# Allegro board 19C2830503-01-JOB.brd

Outline 180.6 x 177.71 mm; copper layers: TOP, L2_GND, L3, L4_PWR, L5, L6_GND, L7_GND, L8, L9_PWR, L10, L11_GND, BOTTOM. Coordinates in mm from the lower left corner of the outline.
Outline path: 0,97.65 arc(0.04,97.84) 0.15,98.01 0.45,98.31 arc(0.62,98.42) 0.81,98.46 9.8,98.46 arc(10.51,98.75) 10.8,99.46 10.8,113.31 arc(10.51,114.02) 9.8,114.31 6.7,114.31 6.7,173.41 8.5,173.41 8.5,176.01 10.8,176.01 10.8,177.71 167,177.71 167,176.71 174.6,176.71 174.6,172.51 180.6,172.51 180.6,30.31 166.24,30.31 166.24,30.81 158,30.81 158,29.21 10.8,29.21 10.8,32.46 arc(10.51,33.17) 9.8,33.46 0.81,33.46 arc(0.62,33.5) 0.45,33.61 0.15,33.91 arc(0.04,34.08) 0,34.27 0,97.65

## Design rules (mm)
net group 25M_MMCX: nets 25M_MMCX 25M_MMCX_R
net group 50OHM(1-4): nets PHYSYNC RADSYNC
net group 5482S_LAN1_LINK_R: nets 5482S_LAN1_LINK_R LAN0_LED_RX
net group 5482S_LAN1_SPEED2_R: nets 5482S_LAN1_SPEED2_R LAN0_LED_LINK100
net group 5482S_LAN2_LINK_R: nets 5482S_LAN2_LINK_R LAN1_LED_RX
net group 5482S_LAN2_SPEED2_R: nets 5482S_LAN2_SPEED2_R LAN1_LED_LINK100
net group AMC_RP1CLKN: nets AMC_RP1CLKN RP1CLKN_C
net group AMC_RP1CLKP: nets AMC_RP1CLKP RP1CLKP_C
net group AMC_TIMO0: nets AMC_TIMO0 TCLKC_P
net group AMCC_P4_PCIE_TX1N: nets AMCC_P4_PCIE_TX1N AMCC_P4_PCIE_TX1N_C
net group AMCC_P4_PCIE_TX1P: nets AMCC_P4_PCIE_TX1P AMCC_P4_PCIE_TX1P_C
net group AMCC_P5_PCIE_TX2N: nets AMCC_P5_PCIE_TX2N AMCC_P5_PCIE_TX2N_C
net group AMCC_P5_PCIE_TX2P: nets AMCC_P5_PCIE_TX2P AMCC_P5_PCIE_TX2P_C
net group AVID_OEZ: nets AVID_OEZ N15783945
net group BSC_JTAG_TCK: nets BSC_JTAG_TCK N13662497
net group CLK1_ELF: nets CLK1_ELF N14872798
net group CLK1_REF_SEL: nets CLK1_REF_SEL N68057721
net group CLK2_ELF: nets CLK2_ELF N14873463
net group CLK2_REF_SEL: nets CLK2_REF_SEL N68049869
net group CLK3_ELF: nets CLK3_ELF N15625345
net group CLK3_REF_SEL: nets CLK3_REF_SEL N15625166
net group CVDD_PWR_MON: nets CVDD_PWR_MON CVDD_PWR_OK
net group DAC_VOUT: nets DAC_VOUT N18495232
net group DDR3_OTHER(10/9-15/13.5): nets SOC_DDR3A_EMRESETN SOC_DDR3B_EMRESETN
net group DIFFPAIR12: nets USB_RXN_R USB_RXP_R
net group DIFFPAIR13: nets USBDN_R USBDP_R
net group DIFFPAIR14: nets USB_TXN_R USB_TXP_R
net group DIFFPAIR26: nets VCTCXO_25M_CLKN_R VCTCXO_25M_CLKP_R
net group DIFFPAIR28: nets USB_DM1 USB_DP1
net group DP_FARM0_UCD_EA1: nets FARM0_UCD_EAN1 FARM0_UCD_EAP1
net group DP_FARM0_UCD_EA2: nets FARM0_UCD_EAN2 FARM0_UCD_EAP2
net group EMIFCE0Z: nets EMIFCE0Z SOC_EMIFCE0Z
net group EMU_EMU_00: nets EMU_EMU_00 EMU_EMU_00_R
net group EMU_EMU_01: nets EMU_EMU_01 EMU_EMU_01_R
net group EMU_TCKRTN: nets EMU_TCKRTN N16762531
net group EMU_TDI: nets EMU_TDI EMU_TDI_R
net group EMU_TDO: nets EMU_TDO EMU_TDO_R
net group EMU_TMS: nets EMU_TMS EMU_TMS_R
net group EMU_TRST#: nets EMU_TRST# EMU_TRST#_R
net group EXP_TP1: nets EXP_TP1 MCU_RESETSTATZ
net group EXP_TP2: nets EXP_TP2 EXT_PS#
net group FAN_PWM: nets FAN_PWM N16114816
net group FARM0_CSN1: nets FARM0_CSN1 N13251183
net group FARM0_CSN2: nets FARM0_CSN2 N13262989
net group FARM0_CSP1: nets FARM0_CSP1 N65094220
net group FARM0_CSP2: nets FARM0_CSP2 N13263135
net group FARM0_FF-1A: nets FARM0_FF-1A FARM0_FF-1A_L
net group FARM0_FF-2A: nets FARM0_FF-2A FARM0_FF-2A_L
net group FARM0_FF-3A: nets FARM0_FF-3A FARM0_FF-3A_L
net group FARM0_FF-4A: nets FARM0_FF-4A FARM0_FF-4A_L
net group FARM0_ILIM1: nets FARM0_ILIM1 N15094693
net group FARM0_ILIM2: nets FARM0_ILIM2 N13263091
net group FARM0_LSENES-1A: nets FARM0_LSENES-1A N13254474
net group FARM0_LSENES-2A: nets FARM0_LSENES-2A N13255208
net group FARM0_LSENES-3A: nets FARM0_LSENES-3A N13256024
net group FARM0_LSENES-4A: nets FARM0_LSENES-4A N13255844
net group FARM0_UCD_EAN4: nets FARM0_UCD_EAN4 N13257002
net group FARM1_FF-1A: nets FARM1_FF-1A FARM1_FF-1A_L
net group FARM1_FF-2A: nets FARM1_FF-2A FARM1_FF-2A_L
net group FARM1_FF-3A: nets FARM1_FF-3A FARM1_FF-3A_L
net group FARM1_FF-4A: nets FARM1_FF-4A FARM1_FF-4A_L
net group FARM1_ILIM2: nets FARM1_ILIM2 N17515515
net group FARM1_LSENES-1A: nets FARM1_LSENES-1A N14336954
net group FARM1_LSENES-2A: nets FARM1_LSENES-2A N14335646
net group FARM1_LSENES-3A: nets FARM1_LSENES-3A N14336112
net group FARM1_LSENES-4A: nets FARM1_LSENES-4A N14336022
net group FULL_RESETZ: nets FULL_RESETZ SW8-P1
net group GPS_ENABLE: nets GPS_ENABLE MCU_GPS_ENABLE
net group GPS_RF: nets GPS_RF N66015127
net group GPS_RTC_CLK: nets GPS_RTC_CLK GPS_RTC_CLK_R
net group GPS_UARTRXD: nets GPS_UARTRXD GPS_UARTRXD_R
net group HYPER0LINKCLKN_C: nets HYPER0_LINK_CLKN HYPER0LINKCLKN_C
net group HYPER0LINKCLKP_C: nets HYPER0_LINK_CLKP HYPER0LINKCLKP_C
net group HYPERLINK0_RXFLCLK: nets HYPERLINK0_RXFLCLK HYPERLINK0_RXFLCLK_R
net group HYPERLINK0_TXPMCLK: nets HYPERLINK0_TXPMCLK HYPERLINK0_TXPMCLK_R
net group HYPERLINK1_RXFLCLK: nets HYPERLINK1_RXFLCLK HYPERLINK1_RXFLCLK_R
net group HYPERLINK1_TXPMCLK: nets HYPERLINK1_TXPMCLK HYPERLINK1_TXPMCLK_R
net group LAN0_LED_LINK10: nets LAN0_LED_LINK10 P0_CONFIG5
net group LAN1_LED_LINK10: nets LAN1_LED_LINK10 P1_CONFIG5
net group LCD_A0: nets LCD_A0 N16319325
net group LED0_DUPLEX: nets LED0_DUPLEX P0_CONFIG3
net group LED_DUPLEX: nets LED_DUPLEX P1_CONFIG3
net group LED_TX: nets LED_TX P1_CONFIG0
net group MAIN_POWER_GOOD: nets MAIN_POWER_GOOD MAIN_POWER_GOOD_R
net group MAIN_POWER_START: nets MAIN_POWER_START MAIN_POWER_START_R
net group MCU_JTAG_TCK: nets MCU_JTAG_TCK N16188479
net group MCU_PA1_U0TX: nets MCU_PA1_U0TX MCU_UART_TX
net group MCU_SPI0_MISO: nets MCU_SPI0_MISO N68025736
net group MCU_SPI0_MOSI: nets MCU_SPI0_MOSI N68025719
net group MCU_SPI1_MOSI: nets MCU_SPI1_MOSI N13012268
net group MCU_U0RX: nets MCU_U0RX MCU_UART_RX
net group MCU_U1RX: nets MCU_U1RX SOC_UART0_TXD_3V3
net group MCUXOSC0: nets MCUXOSC0 MCUXOSC0_R
net group MMC_BLUE_LED: nets MMC_BLUE_LED N16865801
net group MMC_ENABLE_N: nets MMC_ENABLE_N N16053779
net group MMC_RED_LED: nets MMC_RED_LED N16865898
net group N12681649: nets N12681649 N12681653
net group N12681665: nets N12681665 N12681669
net group N13268184: nets N13268184 N13268208
net group N13268308: nets N13268308 N13268312
net group N14335704: nets N14335704 N14335728
net group N14335828: nets N14335828 N14335832
net group N14876495: nets N14876495 N14876735
net group N14876513: nets N14876513 N14876739
net group N14876577: nets N14876577 N14876667
net group N14876581: nets N14876581 N14876671
net group N15443451: nets N15443451 N15443455
net group N15443549: nets N15443549 N15443557
net group N15626537: nets N15626537 N16870591
net group N15633874: nets N15633874 N15633910
net group N15633892: nets N15633892 N15633914
net group N15634110: nets N15634110 N15634136
net group N15634114: nets N15634114 N15634140
net group N15634384: nets N15634384 N15634420
net group N15634388: nets N15634388 N15634424
net group N16169033: nets N16169033 N16169087
net group N16169055: nets N16169055 N16169091
net group N16169113: nets N16169113 N16169139
net group N16169117: nets N16169117 N16169161
net group N16577490: nets N16577490 N16762648
net group N16762689: nets N16762689 N16762695
net group N16826793: nets N16826793 N20002440
net group N16869469: nets N16869469 N68057761
net group N16870184: nets N16870184 N68049909
net group N43929984: nets N43929984 N43929986
net group N43930002: nets N43930002 N43930004
net group N44510240: nets N44510240 N44510256
net group N56425114: nets N56425114 N56425144
net group PCIE_CLKN: nets PCIE_CLKN PCIE_CLKN_R
net group PCIE_CLKP: nets PCIE_CLKP PCIE_CLKP_R
net group PCIECLK_MCU_PD: nets N16316172 PCIECLK_MCU_PD
net group PCIECLK_OE: nets N16572263 PCIECLK_OE
net group PCIECLKN_C: nets PCIECLKN_M PCIECLKN_MR
net group PCIECLKP_C: nets PCIECLKP_M PCIECLKP_MR
net group PHY_P0_XTAL1: nets PHY_P0_XTAL1 PHY_P0_XTAL1_R
net group PHY_P1_XTAL1: nets PHY_P1_XTAL1 PHY_P1_XTAL1_R
net group PLLLOCK_LED: nets N16865403 PLLLOCK_LED
net group PMBUS_ALERT: nets N14715464 PMBUS_ALERT
net group PMBUS_CLK: nets PMBUS_CLK PW_SEQ_SCL
net group PMBUS_CTL: nets N14715500 PMBUS_CTL
net group PMBUS_DAT: nets PMBUS_DAT PW_SEQ_SDA
net group REFCK_N: nets REFCK_N REFCK_N_C
net group REFCK_P: nets REFCK_P REFCK_P_C
net group SOC_EMU_02: nets SOC_EMU_02 SOC_EMU_02_R
net group SOC_EMU_03: nets SOC_EMU_03 SOC_EMU_03_R
net group SOC_EMU_04: nets SOC_EMU_04 SOC_EMU_04_R
net group SOC_EMU_05: nets SOC_EMU_05 SOC_EMU_05_R
net group SOC_EMU_06: nets SOC_EMU_06 SOC_EMU_06_R
net group SOC_EMU_07: nets SOC_EMU_07 SOC_EMU_07_R
net group SOC_EMU_08: nets SOC_EMU_08 SOC_EMU_08_R
net group SOC_EMU_09: nets SOC_EMU_09 SOC_EMU_09_R
net group SOC_EMU_10: nets SOC_EMU_10 SOC_EMU_10_R
net group SOC_EMU_11: nets SOC_EMU_11 SOC_EMU_11_R
net group SOC_EMU_12: nets SOC_EMU_12 SOC_EMU_12_R
net group SOC_EMU_13: nets SOC_EMU_13 SOC_EMU_13_R
net group SOC_EMU_14: nets SOC_EMU_14 SOC_EMU_14_R
net group SOC_EMU_15: nets SOC_EMU_15 SOC_EMU_15_R
net group SOC_EMU_16: nets SOC_EMU_16 SOC_EMU_16_R
net group SOC_EMU_17: nets SOC_EMU_17 SOC_EMU_17_R
net group SOC_EMU_18: nets SOC_EMU_18 SOC_EMU_18_R
net group SOC_EMU_19: nets SOC_EMU_19 SOC_EMU_19_R
net group SOC_EMU_20: nets SOC_EMU_20 SOC_EMU_20_R
net group SOC_EMU_21: nets SOC_EMU_21 SOC_EMU_21_R
net group SOC_EMU_22: nets SOC_EMU_22 SOC_EMU_22_R
net group SOC_EMU_23: nets SOC_EMU_23 SOC_EMU_23_R
net group SOC_EMU_24: nets SOC_EMU_24 SOC_EMU_24_R
net group SOC_EMU_25: nets SOC_EMU_25 SOC_EMU_25_R
net group SOC_EMU_26: nets SOC_EMU_26 SOC_EMU_26_R
net group SOC_EMU_27: nets SOC_EMU_27 SOC_EMU_27_R
net group SOC_EMU_28: nets SOC_EMU_28 SOC_EMU_28_R
net group SOC_EMU_29: nets SOC_EMU_29 SOC_EMU_29_R
net group SOC_EMU_30: nets SOC_EMU_30 SOC_EMU_30_R
net group SOC_EMU_31: nets SOC_EMU_31 SOC_EMU_31_R
net group SOC_EMU_32: nets SOC_EMU_32 SOC_EMU_32_R
net group SOC_EMU_33: nets SOC_EMU_33 SOC_EMU_33_R
net group SOC_GPIO_00: nets SOC_GPIO_00 SOC_GPIO_R00
net group SOC_GPIO_01: nets SOC_GPIO_01 SOC_GPIO_R01
net group SOC_GPIO_02: nets SOC_GPIO_02 SOC_GPIO_R02
net group SOC_GPIO_03: nets SOC_GPIO_03 SOC_GPIO_R03
net group SOC_GPIO_04: nets SOC_GPIO_04 SOC_GPIO_R04
net group SOC_GPIO_05: nets SOC_GPIO_05 SOC_GPIO_R05
net group SOC_GPIO_06: nets SOC_GPIO_06 SOC_GPIO_R06
net group SOC_GPIO_07: nets SOC_GPIO_07 SOC_GPIO_R07
net group SOC_GPIO_08: nets SOC_GPIO_08 SOC_GPIO_R08
net group SOC_GPIO_09: nets SOC_GPIO_09 SOC_GPIO_R09
net group SOC_GPIO_10: nets SOC_GPIO_10 SOC_GPIO_R10
net group SOC_GPIO_11: nets SOC_GPIO_11 SOC_GPIO_R11
net group SOC_GPIO_16: nets SOC_GPIO_16 SOC_GPIO_R16
net group SOC_POWER_GOOD: nets SOC_POWER_GOOD SOC_POWER_GOOD_R
net group SOC_POWER_START: nets SOC_POWER_START SOC_POWER_START_R
net group SOC_RESETSTATZ: nets N16800870 SOC_RESETSTATZ
net group SOC_SSP0_CLK: nets SOC_SSP0_CLK SOC_SSPCK_R
net group SOC_SSP0_MISO: nets N16007057 SOC_SSP0_MISO
net group SOC_SSP0_MOSI: nets SOC_SSP0_MOSI SOC_SSPMOSI_R
net group SOC_SSP1_CLK: nets N68010936 SOC_SSP1_CLK
net group SOC_SSP1_CS0: nets N15613486 SOC_SSP1_CS0
net group SOC_SSP1_MOSI: nets N68010938 SOC_SSP1_MOSI
net group SOC_SSP2_CLK: nets N16755468 SOC_SSP2_CLK
net group SOC_SSP2_CS0: nets N16815045 SOC_SSP2_CS0
net group SOC_SSP2_CS1: nets N16755452 SOC_SSP2_CS1
net group SOC_SSP2_CS2: nets N16755456 SOC_SSP2_CS2
net group SOC_SSP2_CS3: nets N16755460 SOC_SSP2_CS3
net group SOC_SSP2_MISO: nets N16809812 SOC_SSP2_MISO
net group SOC_TIMO1: nets SOC_TIMO1 SOC_TIMO1_R
net group SOC_UART0_TXD_V1P8: nets SOC_UART0_TXD_V1P8 UART0_TXD_R
net group SOC_UART1_RTS_V1P8: nets SOC_UART1_RTS_V1P8 UART1_RTS_R
net group SOC_UART1_TXD_1V8: nets SOC_UART1_TXD_1V8 UART1_TXD_R
net group SOC_XFI_CLKN: nets SOC_XFI_CLKN SOC_XFI_CLKN_R
net group SOC_XFI_CLKP: nets SOC_XFI_CLKP SOC_XFI_CLKP_R
net group SOCCLKSEL_R: nets SOC_CORECLKSEL SOCCLKSEL_R
net group SPI: nets N16809810 SOC_SSP2_MOSI
net group SW7-P1: nets SW7-P1 WARM_RESETZ
net group TCLKB_N: nets TCLKB_N TCLKB_N_C
net group TCLKB_P: nets TCLKB_P TCLKB_P_C
net group TCLKD_N: nets TCLKD_N TCLKD_N_C
net group TCLKD_P: nets TCLKD_P TCLKD_P_C
net group TRIP1: nets TRIP1 TRIP3
net group UCD_PWR_MON: nets UCD_PWR_MON UCD_PWR_OK
net group URTM_PS#: nets URTM_PS# URTM_PS#_R
net group USB: nets USB_TXN USB_TXP
net group USB_CLKN: nets USB_CLKN USB_CLKN_R
net group USB_CLKP: nets USB_CLKP USB_CLKP_R
net group VCC0V75_EN: nets VCC0V75_EN VCC0V75_EN_R
net group VCC1V2_EN: nets VCC1V2_EN VCC1V2_EN_R
net group VCC2V5_EN: nets VCC2V5_EN VCC2V5_EN_R
net group VCC3_LCD: nets N14810291 VCC3_LCD
net group VCC3V3_AUX_EN: nets VCC3_AUX_EN_R VCC3V3_AUX_EN
net group VCTCXO_25M_CLKN: nets VCTCXO_25M_CLKN VCTCXO_25M_CLKN_C
net group VCTCXO_25M_CLKP: nets VCTCXO_25M_CLKP VCTCXO_25M_CLKP_C
net group VID_OEZ: nets N15783905 VID_OEZ
net group VPP1V8: nets N16969569 VPP1V8_MON
net group 5482S_LAN1_SPEED1_R: nets 5482S_LAN1_SPEED1_R LAN0_LED_LINK1000 P0_CONFIG1 P0_CONFIG4
net group 5482S_LAN2_SPEED1_R: nets 5482S_LAN2_SPEED1_R LAN1_LED_LINK1000 P1_CONFIG1 P1_CONFIG4
net group AIF0_RXN_C: nets AIF0_RXN_C
net group AIF0_RXP_C: nets AIF0_RXP_C
net group AIF1_RXN_C: nets AIF1_RXN_C
net group AIF1_RXP_C: nets AIF1_RXP_C
net group AIF2_RXN_C: nets AIF2_RXN_C
net group AIF2_RXP_C: nets AIF2_RXP_C
net group AIF3_RXN_C: nets AIF3_RXN_C
net group AIF3_RXP_C: nets AIF3_RXP_C
net group AIF4_RXN_C: nets AIF4_RXN_C
net group AIF4_RXP_C: nets AIF4_RXP_C
net group AIF5_RXN_C: nets AIF5_RXN_C
net group AIF5_RXP_C: nets AIF5_RXP_C
net group ALTCORECLKN_C: nets ALT_CORE_CLKN
net group ALTCORECLKP_C: nets ALT_CORE_CLKP
net group ARMCLKN_C: nets ARM_CLKN
net group ARMCLKP_C: nets ARM_CLKP
net group AT_CLKN: nets AT_CLKN
net group AT_CLKP: nets AT_CLKP
net group BSC_JTAG_SRSTN: nets BSC_JTAG_SRSTN MCU_SRSTN_R N13662509
net group BSC_JTAG_TDI: nets BSC_JTAG_TDI MCU_JTAG_TDI N13662505
net group BSC_JTAG_TDO: nets BSC_JTAG_TDO MCU_JTAG_TDO N13662501
net group BSC_JTAG_TMS: nets BSC_JTAG_TMS MCU_JTAG_TMS N13662493
net group CLK_DIFF: nets VCC3V3_PCIE
net group CLK_SINGLE: nets CLK1_SYNC CLK2_SYNC GTX_CLK GTX_CLK_0 P0_CLKSEL P1_CLKSEL REFCLK1_PD# REFCLK2_PD# SIM_CLK TX_CLK TX_CLK_0
net group DDR3ACLKN_C: nets DDR3A_CLKN
net group DDR3ACLKP_C: nets DDR3A_CLKP
net group DDR3BCLKN_C: nets DDR3B_CLKN
net group DDR3BCLKP_C: nets DDR3B_CLKP
net group DSP_SCL_AMC: nets DSP_SCL_AMC EXP_SCL2_3V3 SOC_SCL_RTM
net group DSP_SDA_AMC: nets DSP_SDA_AMC EXP_SDA2_3V3 SOC_SDA_RTM
net group EMU_TCK: nets EMU_TCK EMU_TCK_R N17260565
net group FARM0_UCD_EAN3: nets FARM0_UCD_EAN3 FARM0_UCD_EAP3 N13256834
net group FARM1_AVGG2: nets FARM1_AVGG2
net group FARM1_CSN2: nets FARM1_CSN2 FARM1_CSP2 N14340048 N14340304 N14340850 N14340854
net group FARM1_SW_SHAPE1: nets N14634249
net group FARM1_UCD_EAN1: nets FARM1_UCD_EAN1 FARM1_UCD_EAP1 N14335250
net group FARM1_UCD_EAN2: nets FARM1_UCD_EAN2 FARM1_UCD_EAP2 N14336826
net group FARM1_UCD_EAN3: nets FARM1_UCD_EAN3 FARM1_UCD_EAP3 N14336882
net group FARM1_UCD_EAN4: nets FARM1_UCD_EAN4 FARM1_UCD_EAP4 N14336966
net group FARM1_UCD_EN: nets FARM1_UCD_EN FARM1_UCD_EN_L FARM1_UCD_EN_R
net group FT2232HL_RESET#1: nets FT2232HL_RESET#1 N12620052 N12620068 N12620494 N15576101
net group HEAD_UCD_CNTRL_L: nets HEAD_UCD_CNTRL_L UCD9244_EN UCD9244_EN_R
net group HYPER1LINKCLKN_C: nets HYPER1_LINK_CLKN
net group HYPER1LINKCLKP_C: nets HYPER1_LINK_CLKP
net group LAN: nets LAN0_TRD2_0N LAN0_TRD2_0P LAN0_TRD2_1N LAN0_TRD2_1P LAN0_TRD2_2N LAN0_TRD2_2P LAN0_TRD2_3N LAN0_TRD2_3P LAN1_TRD2_0N LAN1_TRD2_0P LAN1_TRD2_1N LAN1_TRD2_1P LAN1_TRD2_2N LAN1_TRD2_2P LAN1_TRD2_3N LAN1_TRD2_3P
net group MCU_RESET_SWZ: nets MCU_RESET_SWZ
net group MCU_SPI0: nets MCU_SPI0_CLK MCU_SPI0_CLK_1V8 MCU_SPI0_CS0Z MCU_SPI0_CS1Z MCU_SPI0_CS3Z MCU_SPI0_CS4Z MCU_SPI0_MISO_1V8 MCU_SPI0_MOSI_1V8
net group MCU_SPI1: nets MCU_SPI1_CLK
net group MMC_GA0: nets MMC_GA0 MMC_GA1 MMC_GA2 MMC_GAPU
net group N17761475: nets N56424980 N56425122 N56425140
net group N44510100: nets N44510176
net group PHY_RSTZ: nets PHY_RSTZ R_P0_LAN_RSTZ R_P1_LAN_RSTZ
net group SIM_IO: nets SIM_IO
net group SMBUS: nets SMB_SCL_IPMBL SMB_SDA_IPMBL SOC_MDC SOC_MDC_3V3 SOC_MDIO SOC_MDIO_3V3
net group SOC_GPIO_12: nets N16761112 SOC_GPIO_12 SOC_GPIO_R12
net group SOC_GPIO_13: nets N16761582 SOC_GPIO_13 SOC_GPIO_R13
net group SOC_GPIO_14: nets N16757437 SOC_GPIO_14 SOC_GPIO_R14
net group SOC_GPIO_15: nets N16758697 SOC_GPIO_15 SOC_GPIO_R15
net group SOC_SGMII0_RXN: nets SOC_SGMII0_RXN
net group SOC_SGMII0_RXP: nets SOC_SGMII0_RXP
net group SOC_SGMII0_TXN: nets SOC_SGMII0_TXN_C
net group SOC_SGMII0_TXP: nets SOC_SGMII0_TXP_C
net group SOC_SGMII1_RXN: nets SOC_SGMII1_RXN
net group SOC_SGMII1_RXP: nets SOC_SGMII1_RXP
net group SOC_SGMII1_TXN: nets SOC_SGMII1_TXN_C
net group SOC_SGMII1_TXP: nets SOC_SGMII1_TXP_C
net group SOC_SSP2_MOSI: nets N16755464
net group SOC_TIMO0: nets SOC_TIMO0 SOC_TIMO0_R TCLKC_N
net group SRIOSGMIICLKN_C: nets SRIO_SGMII_CLKN
net group SRIOSGMIICLKP_C: nets SRIO_SGMII_CLKP
net group UART: nets RS232_RX RS232_TX SOC_UART0_RXD_3V3
net group VCC5: nets N16826901 N16827414 VCC5_MON
net group VCC5_EN: nets VCC5_EN VCC5_EN_R1 VCC5_EN_R2
net group VCC5_VBUS: nets N12619718 N15576385 VCC5_VBUS
net group VCCA0V75: nets VCCA0V75_MON

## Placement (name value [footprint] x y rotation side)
AMC1  -  [GF-AMC-B]  2.05 65.96 90 top
ATT  DTSA-63K-V  [SW_2P_DTSA-63K-V_D]  176.75 124.16 90 top
B1  120_100MHz  [L0603]  113.16 173.74 90 bottom
B2  120_100MHz  [L0603]  125.09 173.86 270 top
B3  120_100MHz  [L0603]  129.29 173.86 90 top
B4  120_100MHz  [L0402]  170.18 171.07 270 top
B5  1K_100MHz  [L0603]  165.74 164.85 270 top
B6  1K_100MHz  [L0603]  165.74 162.94 270 top
B7  220_100MHz  [L0402]  128.65 133.86 180 top
B8  120_100MHz  [L0402]  123.06 133.48 180 top
B9  2200pF  [L_3P_70_63X35]  73.28 135.38 270 top
B10  2200pF  [L_3P_70_63X35]  40.77 125.98 90 top
B11  2200pF  [L_3P_70_63X35]  70.74 135.38 270 top
B12  2200pF  [L_3P_70_63X35]  43.08 124.79 0 top
B13  2200pF  [L_3P_70_63X35]  120.02 125.86 0 top
B14  2200pF  [L_3P_70_63X35]  89.13 108.61 180 top
B15  2200pF  [L_3P_70_63X35]  107.57 117.09 90 top
B16  470_100MHz  [L0603]  78.11 86.61 0 bottom
B17  100_100MHz  [L0603]  80.16 83.85 0 bottom
B20  100_100MHz  [L0603]  37.97 74.17 90 bottom
B22  90_100MHZ  [ACM2012]  162 115.85 0 top
B23  2200pF  [L_3P_70_63X35]  17.91 113.16 0 top
B24  90_100MHZ  [ACM2012]  162.05 111.76 0 top
B25  2200pF  [L_3P_70_63X35]  45.97 122.3 270 top
B27  120_100MHz  [L0402]  149.99 102.49 180 top
B28  0.1uF  [L_3P_87_79X53]  32.77 99.95 270 bottom
B29  0.1uF  [L_3P_87_79X53]  34.92 92.2 270 bottom
B30  120_100MHz  [L0402]  153.8 91.06 0 top
B31  2200pF  [L_3P_70_63X35]  24.51 89.92 0 top
B32  470_100MHz  [L0603]  79.04 75.56 180 bottom
B33  120_100MHz  [L0402]  149.99 78.1 180 top
B34  120_100MHz  [L0402]  153.8 76.19 0 top
B38  470_100MHz  [L0603]  64.16 74.8 180 bottom
B39  2200pF  [L_3P_70_63X35]  126.24 67.31 270 top
B41  470_100MHz  [L0603]  38.99 70.61 270 top
B43  1212_BEAD_0  [L0603]  36.7 55.25 270 top
B44  2200pF  [L_3P_70_63X35]  83.06 122.33 270 bottom
B45  470_100MHz  [L0603]  67.39 112.6 180 bottom
B46  1212_BEAD_0  [L0603]  35.31 82.8 0 bottom
B47  2200pF  [L_3P_70_63X35]  136.25 80.34 270 top
B48  120_100MHz  [L0402]  70.87 89.41 180 bottom
C1  0.1uF  [C0402]  160.88 171.07 0 bottom
C2  0.1uF  [C0402]  106.43 173.99 270 top
C3  0.1uF  [C0402]  147.07 173.23 180 top
C4  0.1uF  [C0402]  120.14 172.72 0 top
C5  0.1uF  [C0402]  127.89 172.21 270 top
C6  0.1uF  [C0402]  130.94 172.21 90 top
C7  10uF  [C0603]  161.67 171.07 270 top
C8  10uF  [C0805]  122.05 170.81 180 top
C9  1200pF  [C0603]  105.03 169.04 90 top
C10  0.01uF  [C0402]  109.47 173.99 180 bottom
C11  10uF  [C0805]  107.57 173.86 0 bottom
C12  10uF  [C0603]  144.83 169.65 180 top
C13  0.1uF  [C0402]  111.38 168.91 270 top
C14  8200pF  [C0603]  125.6 168.78 90 top
C15  10uF  [C0603]  162.69 167.51 180 top
C16  0.01uF  [C0402]  107.31 168.15 0 top
C17  0.1uF  [C0402]  160.66 167.77 90 top
C18  560pF  [C0402]  108.33 166.5 270 top
C19  0.1uF  [C0402]  144.53 166.12 270 top
C20  0.01uF  [C0402]  161.67 164.97 180 top
C21  0.1uF  [C0402]  163.07 164.97 180 top
C22  0.1uF  [C0402]  133.3 165.58 0 top
C23  10uF  [C0603]  104.14 164.85 270 top
C24  0.1uF  [C0402]  144.53 164.59 270 top
C25  0.1uF  [C0402]  161.8 162.94 180 top
C26  0.01uF  [C0402]  163.19 162.94 180 top
C27  0.1uF  [C0402]  168.66 161.93 90 bottom
C28  33pF  [C0402]  163.96 161.29 270 top
C29  0.1uF  [C0402]  107.7 159.64 0 top
C30  10uF  [C0603]  144.91 159.64 180 top
C31  10uF  [C0603]  106.05 159.51 0 top
C32  10pF  [C0402]  88.52 158.88 270 top
C33  33pF  [C0402]  161.93 161.29 90 top
C34  0.1uF  [C0402]  134.37 157.35 90 top
C35  0.1uF  [C0402]  149.35 157.35 180 top
C36  0.1uF  [C0402]  152.53 157.35 0 top
C37  0.1uF  [C0402]  156.21 157.35 0 top
C38  2.2uF  [C0402]  158.62 157.12 90 top
C39  NL/22uF  [C_2P_244_287X177]  115.95 156.46 270 top
C40  0.1uF  [C0402]  169.8 154.18 270 top
C41  100uF  [OEC-D]  128.4 153.75 270 top
C42  2.2uF  [C0402]  169.8 152.78 90 top
C43  22uF  [C1206-1]  112.62 150.52 270 top
C44  0.1uF  [C0402]  114.78 150.27 180 top
C45  0.1uF  [C0402]  145.8 149.1 180 top
C46  47uF  [C0805]  135.38 147.83 270 top
C47  47uF  [C0805]  135.45 145.43 270 top
C48  22uF  [C1206-1]  48.26 148.39 270 top
C49  0.1uF  [C0402]  50.93 145.92 270 bottom
C50  0.22uF  [C0402]  87.6 147.68 90 top
C51  0.22uF  [C0402]  76.17 147.93 90 top
C52  47uF  [C0805]  72.03 147.9 270 top
C53  47uF  [C0805]  135.45 143.02 270 top
C54  0.01uF  [C0402]  167.13 40.89 90 top
C55  0.1uF  [C0402]  168.53 142.75 270 top
C56  47uF  [C0805]  72.03 145.49 270 top
C57  4.7uF  [C1206-1]  75.29 144.88 270 top
C58  1000pF  [C0402]  86.87 144.78 0 top
C59  47uF  [C0805]  137.54 140.34 270 top
C60  0.22uF  [C0603]  60.33 143.51 0 top
C61  1uF  [C0603]  118.72 140.11 180 top
C62  0.1uF  [C0402]  121.51 140.11 180 top
C63  0.22uF  [C0603]  124.43 140.11 0 top
C64  47uF  [C0805]  72.03 143.08 270 top
C65  470uF  [C_2P_244_287X177_H110]  130.05 139.29 270 top
C66  100uF  [C1206-1]  65.43 141.81 180 top
C67  0.1uF  [C0402]  59.31 141.22 270 top
C68  47uF  [C0805]  137.54 137.79 270 top
C69  0.01uF  [C0402]  153.72 137.24 90 top
C70  10pF  [C0402]  160.3 137.19 270 top
C71  10pF  [C0402]  162.59 137.19 270 top
C72  0.01uF  [C0402]  155.83 136.91 0 top
C73  0.01uF  [C0402]  157.99 136.91 0 top
C74  1uF  [C0603]  55.75 139.5 270 top
C75  470uF  [C_2P_244_287X177_H110]  64.36 137.97 270 top
C76  4.7uF  [C0603]  126.11 133.86 270 top
C77  0.01uF  [C0402]  168.4 134.37 270 top
C78  0.01uF  [C0402]  105.66 132.21 180 top
C79  1000pF  [C0402]  107.31 132.21 0 top
C80  0.01uF  [C0402]  110.49 131.95 270 top
C81  560pF  [C0402]  112.52 131.95 270 top
C82  560pF  [C0402]  114.55 131.95 270 top
C83  560pF  [C0402]  116.59 131.95 270 top
C84  560pF  [C0402]  118.62 131.95 270 top
C85  0.01uF  [C0402]  125.22 131.95 180 top
C86  0.1uF  [C0402]  126.62 131.95 0 top
C87  0.1uF  [C0402]  128.4 131.7 270 top
C88  1uF  [C0402]  71.93 132.84 270 top
C89  0.1uF  [C0402]  71.93 131.44 90 top
C90  0.01uF  [C0402]  105.41 130.18 180 top
C91  1uF  [C0402]  118.49 128.91 180 top
C92  0.1uF  [C0402]  85.47 131.83 270 top
C93  1uF  [C0402]  42.55 126.75 0 top
C94  0.1uF  [C0402]  43.81 126.75 180 top
C95  0.1uF  [C0402]  69.85 132.84 270 top
C96  1uF  [C0402]  69.85 131.44 90 top
C97  47uF  [C0805]  78.92 131.65 90 top
C98  47uF  [C0805]  89.81 132.11 270 top
C99  0.01uF  [C0402]  105.41 128.14 180 top
C100  2.2uF  [C0402]  119.89 128.02 180 top
C101  0.1uF  [C0402]  84.07 108.71 0 top
C102  0.1uF  [C0402]  85.47 108.71 0 top
C103  1uF  [C0402]  86.74 108.71 180 top
C104  4.7uF  [C0603]  82.3 130.3 90 top
C105  4.7uF  [C0603]  85.47 130.3 270 top
C106  1uF  [C0402]  45.34 125.48 180 top
C107  0.1uF  [C0402]  46.74 125.48 0 top
C108  10uF  [C0603]  68.07 131.83 0 top
C109  1000pF  [C0402]  105.41 126.11 0 top
C110  47uF  [C0805]  78.92 129.11 90 top
C111  47uF  [C0805]  89.81 129.57 270 top
C112  33nF  [C0402]  66.67 134.37 180 top
C113  10uF  [C0603]  43.56 122.17 180 top
C114  0.1uF  [C0402]  120.4 123.95 270 top
C115  0.1uF  [C0402]  82.04 131.83 270 bottom
C116  560pF  [C0402]  85.47 131.7 90 bottom
C117  2200pF  [C0402]  41.53 118.62 270 top
C118  330pF  [C0402]  43.43 117.22 90 top
C119  NL/0.1uF  [C0402]  105.16 122.94 270 top
C120  0.01uF  [C0402]  171.32 122.56 90 top
C121  0.01uF  [C0402]  98.68 121.41 180 top
C122  0.01uF  [C0402]  100.08 121.41 180 top
C123  3.3uF  [C0805]  63.37 133.81 180 top
C124  NL/0.1uF  [C0402]  105.16 121.54 90 top
C125  NL/0.1uF  [C0402]  119 121.16 90 top
C126  0.1uF  [C0402]  62.74 130.56 180 top
C127  0.1uF  [C0402]  154.18 119.89 0 top
C128  0.1uF  [C0402]  155.45 119.89 180 top
C129  0.1uF  [C0402]  156.84 119.89 180 top
C130  0.1uF  [C0402]  158.24 119.89 0 top
C131  0.01uF  [C0402]  126.11 119.25 180 top
C132  0.1uF  [C0402]  141.99 119.13 180 top
C133  0.1uF  [C0402]  148.89 119.13 180 top
C134  1uF  [C0402]  58.72 124.33 0 bottom
C135  0.1uF  [C0402]  45.97 116.1 90 top
C136  0.1uF  [C0402]  119 118.49 270 top
C137  1uF  [C0402]  60.07 126.24 270 top
C138  0.1uF  [C0402]  60.2 124.71 270 bottom
C139  0.1uF  [C0402]  60.2 123.32 270 bottom
C140  100pF  [C0402]  105.66 117.98 180 top
C141  0.1uF  [C0402]  53.21 124.33 180 top
C142  0.1uF  [C0402]  54.61 124.33 180 top
C143  10uF  [C0603]  146.69 117.09 0 top
C144  10uF  [C0603]  139.95 116.97 0 top
C145  NL/0.1uF  [C0402]  113.92 116.46 0 top
C146  0.1uF  [C0402]  105.66 115.95 180 top
C147  0.1uF  [C0402]  97.03 120.52 270 top
C148  10uF  [C0603]  146.69 113.92 180 top
C149  0.1uF  [C0402]  97.03 119 270 top
C150  10uF  [C0603]  139.95 113.79 180 top
C151  10uF  [C0603]  14.61 113.16 270 top
C152  0.1uF  [C0402]  78.23 83.06 270 bottom
C153  0.1uF  [C0402]  38.35 75.69 90 bottom
C155  0.1uF  [C0402]  78.74 90.93 90 bottom
C156  0.1uF  [C0402]  80.77 89.15 270 bottom
C157  0.1uF  [C0402]  80.77 87.76 270 bottom
C158  0.1uF  [C0402]  141.48 111.38 0 top
C159  0.1uF  [C0402]  148.21 110.87 0 top
C160  2.2uF  [C0402]  110.86 110.8 0 top
C161  0.1uF  [C0402]  109.42 110.79 0 top
C162  0.1uF  [C0402]  45.97 120.02 90 top
C163  100pF  [C0402]  45.97 118.62 270 top
C164  0.1uF  [C0402]  155.57 109.73 180 top
C165  1uF  [C0402]  156.97 109.73 0 top
C166  0.1uF  [C0402]  14.22 109.6 90 top
C167  0.1uF  [C0402]  14.22 108.08 90 top
C168  1uF  [C0402]  94.41 114.5 180 top
C169  10uF  [C0603]  85.98 112.27 180 top
C170  0.1uF  [C0402]  61.72 112.52 0 top
C171  0.1uF  [C0402]  68.96 113.54 0 bottom
C172  0.022uF  [C0402]  88.77 112.52 180 top
C173  100uF  [OEC-D]  155.35 105.23 90 top
C174  0.1uF  [C0402]  63.25 108.71 0 top
C175  0.1uF  [C0402]  64.64 108.71 0 top
C176  0.1uF  [C0402]  65.91 108.71 180 top
C177  0.1uF  [C0402]  67.31 108.71 180 top
C178  0.1uF  [C0402]  68.58 108.71 0 top
C179  0.1uF  [C0402]  69.98 108.71 0 top
C180  0.1uF  [C0402]  134.37 104.52 270 top
C181  1uF  [C0603]  18.03 104.39 180 top
C182  0.22uF  [C0402]  16.38 104.01 0 top
C183  0.1uF  [C0402]  163.32 104.01 0 top
C184  0.1uF  [C0402]  60.2 112.52 0 top
C185  4.7uF  [C0603]  147.19 103.89 270 top
C186  1000pF  [C0402]  20.19 103.63 90 top
C187  0.1uF  [C0402]  58.8 108.71 0 top
C188  4.7uF  [C0603]  147.07 102.11 270 top
C189  0.1uF  [C0402]  138.56 101.98 270 top
C190  0.1uF  [C0402]  44.07 102.11 90 top
C191  0.1uF  [C0402]  57.4 108.71 0 top
C192  0.01uF  [C0402]  140.72 100.97 0 top
C193  0.1uF  [C0402]  144.65 100.84 270 top
C194  4.7uF  [C0603]  151.38 100.84 90 top
C195  0.01uF  [C0402]  138.56 100.33 270 top
C196  47uF  [C0805]  32.38 100.08 180 top
C197  47uF  [C0805]  32.38 104.14 0 top
C198  0.1uF  [C0402]  142.19 100 0 top
C199  0.1uF  [C0402]  44.07 100.84 90 top
C200  0.1uF  [C0402]  45.97 99.95 90 top
C201  0.01uF  [C0402]  153.8 99.42 90 top
C202  0.01uF  [C0402]  149.61 98.43 270 top
C203  0.1uF  [C0402]  45.97 98.55 90 top
C204  0.1uF  [C0402]  143.13 97.97 180 top
C205  0.1uF  [C0402]  124.46 97.79 90 top
C206  0.01uF  [C0402]  140.64 97.46 270 top
C207  10uF  [C0603]  34.67 96.65 180 top
C208  0.1uF  [C0402]  35.94 99.44 0 bottom
C209  0.01uF  [C0402]  153.8 96.65 90 top
C210  0.1uF  [C0402]  43.56 98.43 90 top
C211  0.1uF  [C0402]  138.18 96.14 270 top
C212  4.7uF  [C0603]  142.62 96.01 90 top
C213  4.7uF  [C0603]  145.8 95.88 270 top
C214  0.01uF  [C0402]  153.8 95.25 90 top
C215  0.1uF  [C0402]  43.56 97.03 90 top
C216  0.1uF  [C0402]  45.97 96.9 90 top
C217  0.01uF  [C0402]  153.8 93.85 270 top
C218  0.1uF  [C0402]  45.97 95.63 90 top
C219  0.1uF  [C0402]  47.24 92.33 90 bottom
C220  0.01uF  [C0402]  153.8 92.46 270 top
C221  0.22uF  [C0402]  16.38 92.08 0 top
C222  47uF  [C0805]  32.51 92.33 180 top
C223  47uF  [C0805]  32.38 96.52 0 top
C224  0.1uF  [C0402]  47.24 90.93 90 bottom
C225  0.1uF  [C0402]  36.58 91.82 0 bottom
C226  4.7uF  [C1206-1]  18.54 90.55 270 top
C227  0.1uF  [C0402]  44.83 87.76 90 bottom
C228  2.2uF  [C0402]  21.84 89.03 270 top
C229  0.1uF  [C0402]  44.83 86.36 90 bottom
C230  0.1uF  [C0402]  26.16 88.01 0 top
C231  NL/0.1uF  [C0402]  31.24 87.88 180 top
C232  1uF  [C0402]  20.83 87.76 270 top
C233  0.1uF  [C0402]  47.24 82.55 90 bottom
C234  0.1uF  [C0402]  45.97 93.34 90 top
C235  0.1uF  [C0402]  47.24 81.15 90 bottom
C236  560pF  [C0402]  20.19 86.11 0 top
C237  0.1uF  [C0402]  45.97 92.08 90 top
C238  0.1uF  [C0402]  45.97 88.14 90 top
C239  560pF  [C0402]  20.19 84.07 0 top
C240  0.1uF  [C0402]  43.56 86.21 90 top
C241  0.1uF  [C0402]  45.97 86.74 90 top
C242  22uF  [C0805]  109.51 82.69 90 top
C243  0.1uF  [C0402]  43.56 84.81 90 top
C244  560pF  [C0402]  20.19 82.04 0 top
C245  0.1uF  [C0402]  45.97 84.07 90 top
C246  0.01uF  [C0402]  153.8 81.91 90 top
C247  0.1uF  [C0402]  124.33 81.66 180 top
C248  0.1uF  [C0402]  45.97 82.68 90 top
C249  10uF  [C0603]  37.97 72.26 270 bottom
C250  1uF  [C0402]  109.13 80.27 270 top
C251  NL/0.1uF  [C0402]  35.69 80.14 90 top
C252  560pF  [C0402]  20.19 80.01 0 top
C253  0.1uF  [C0402]  43.56 82.42 90 top
C254  4.7uF  [C0603]  147.07 79.88 270 top
C255  0.01uF  [C0402]  153.8 78.99 270 top
C256  22uF  [C0805]  125.09 78.87 270 top
C257  0.1uF  [C0402]  43.56 81.03 90 top
C258  0.1uF  [C0402]  45.97 80.39 90 top
C259  0.1uF  [C0402]  78.87 77.85 270 bottom
C260  0.01uF  [C0402]  15.37 77.98 270 top
C261  4.7uF  [C0603]  147.07 77.85 270 top
C262  0.1uF  [C0402]  138.56 77.59 270 top
C263  0.01uF  [C0402]  153.8 77.59 270 top
C264  22uF  [C0805]  109.64 77.23 90 top
C265  0.1uF  [C0402]  45.97 78.99 90 top
C266  1uF  [C0402]  124.75 76.84 90 top
C267  0.1uF  [C0402]  45.97 77.6 90 top
C268  0.01uF  [C0402]  140.72 76.57 0 top
C269  1000pF  [C0402]  17.53 76.45 270 top
C270  0.1uF  [C0402]  144.65 76.44 270 top
C271  4.7uF  [C0603]  151.13 76.2 90 top
C272  0.1uF  [C0402]  68.02 74.32 90 bottom
C273  0.01uF  [C0402]  138.56 75.94 270 top
C274  0.1uF  [C0402]  142.19 75.61 0 top
C275  1uF  [C0402]  124.75 75.45 90 top
C276  0.1uF  [C0402]  45.97 76.2 90 top
C277  0.1uF  [C0402]  43.56 76.07 90 top
C278  0.01uF  [C0402]  149.61 74.03 270 top
C279  1000pF  [C0402]  22.23 73.91 0 top
C280  1000pF  [C0402]  23.62 73.91 180 top
C281  1000pF  [C0402]  25.02 73.91 180 top
C282  0.1uF  [C0402]  26.42 73.91 0 top
C283  NL/0.1uF  [C0402]  29.08 73.91 0 top
C284  NL/0.1uF  [C0402]  33.02 73.91 0 top
C285  1uF  [C0402]  110.02 73.8 270 top
C287  0.1uF  [C0402]  143.13 73.57 180 top
C288  0.1uF  [C0402]  43.56 74.8 90 top
C289  22uF  [C0805]  125 73.29 270 top
C290  0.01uF  [C0402]  140.64 73.07 270 top
C291  0.1uF  [C0402]  44.96 65.15 270 bottom
C292  0.22uF  [C0603]  21.46 64.52 90 top
C293  4.7uF  [C1206-1]  24.59 65.15 180 bottom
C294  0.01uF  [C0402]  153.8 71.88 90 top
C295  4.7uF  [C0603]  142.62 71.62 90 top
C296  0.1uF  [C0402]  138.05 71.5 270 top
C297  4.7uF  [C0603]  145.8 71.49 270 top
C299  22uF  [C0805]  109.38 71.13 90 top
C300  0.1uF  [C0402]  44.96 63.75 270 bottom
C301  0.1uF  [C0402]  128.02 68.83 0 top
C302  0.1uF  [C0402]  46.1 71.75 90 top
C303  0.1uF  [C0402]  65.94 74.02 90 bottom
C304  1uF  [C0402]  109.89 68.72 270 top
C305  1uF  [C0402]  124.46 68.58 90 top
C306  22uF  [C1206-1]  17.53 70.23 270 top
C307  0.1uF  [C0402]  46.1 70.36 90 top
C308  0.1uF  [C0402]  47.24 67.06 270 bottom
C309  0.1uF  [C0402]  43.56 69.98 90 top
C311  0.1uF  [C0402]  47.24 65.79 270 bottom
C312  0.1uF  [C0402]  43.56 68.58 90 top
C313  47uF  [C0805]  28.7 63.12 270 bottom
C314  1uF  [C0603]  24.46 71.73 90 top
C315  10uF  [C0603]  125.48 64.64 270 top
C316  0.1uF  [C0402]  39.37 69.09 270 top
C317  0.1uF  [C0402]  46.1 67.94 90 top
C318  0.1uF  [C0402]  125.48 62.99 90 top
C319  0.1uF  [C0402]  46.1 66.55 90 top
C321  0.1uF  [C0402]  139.01 59.33 270 bottom
C322  1uF  [C0402]  152.15 59.82 270 top
C323  0.1uF  [C0402]  44.32 64.39 90 top
C324  0.1uF  [C0402]  44.32 62.99 90 top
C325  0.1uF  [C0402]  137.26 61.37 180 top
C326  100uF  [C1206-1]  34.67 60.71 270 bottom
C327  470uF  [C_2P_244_287X177_H110]  32.51 61.09 0 top
C328  4.7uF  [C0603]  29.34 60.45 180 bottom
C329  1uF  [C0402]  148.21 60.83 90 top
C330  1uF  [C0402]  152.15 56.77 90 top
C331  0.1uF  [C0402]  67.69 56.13 180 top
C332  0.1uF  [C0402]  124.33 56.26 0 top
C333  10uF  [C0603]  33.53 55.25 270 top
C334  0.1uF  [C0402]  131.06 54.97 90 top
C335  1uF  [C0402]  144.53 40.89 0 bottom
C336  10uF  [C0603]  110.85 46.96 0 top
C337  0.1uF  [C0402]  139.57 53.47 90 top
C338  0.1uF  [C0402]  152.15 51.44 270 top
C339  10uF  [C0603]  106.17 51.31 90 top
C340  0.1uF  [C0402]  26.54 50.8 0 top
C341  0.1uF  [C0402]  139.57 52.07 90 top
C342  0.1uF  [C0402]  103.89 49.66 180 top
C343  10uF  [C0603]  106.17 49.66 90 top
C344  2.2uF  [C0603]  101.6 49.53 90 top
C345  0.1uF  [C0402]  37.97 49.15 270 bottom
C346  10uF  [C0805]  15.37 50.42 90 bottom
C347  0.1uF  [C0402]  134.75 49.02 270 top
C348  1000pF  [C0402]  20.83 47.88 90 top
C349  10uF  [C0603]  101.6 47.88 90 top
C350  560pF  [C0402]  37.97 50.55 90 bottom
C351  1uF  [C0603]  17.27 47.5 180 top
C352  0.1uF  [C0402]  124.88 47.25 0 top
C353  0.1uF  [C0402]  126.27 47.25 0 top
C354  0.1uF  [C0603]  15.24 48.39 270 bottom
C355  0.1uF  [C0402]  101.85 46.36 270 top
C356  0.1uF  [C0402]  100.33 44.96 270 top
C357  1uF  [C0402]  109.09 44.45 0 top
C358  1uF  [C0402]  110.49 44.45 0 top
C359  1uF  [C0402]  111.89 44.45 0 top
C360  0.1uF  [C0402]  35.94 43.56 270 bottom
C361  0.1uF  [C0402]  102.62 43.56 90 top
C362  0.1uF  [C0402]  134.75 106.3 90 bottom
C363  0.01uF  [C0402]  107.19 42.29 90 top
C364  0.1uF  [C0402]  102.62 42.16 270 top
C365  47uF  [C0805]  110.62 42.04 90 top
C366  0.1uF  [C0402]  25.65 41.66 0 top
C367  0.1uF  [C0402]  32.64 41.66 0 top
C368  100uF  [C1206-1]  116.97 41.27 0 top
C369  NL/1.5pF  [C0402]  171.96 39.24 90 top
C370  1000pF  [C0402]  169.93 42.04 270 top
C371  0.1uF  [C0402]  125.73 40.13 90 top
C372  10uF  [C0603]  41.53 43.18 180 bottom
C373  47uF  [C0805]  110.62 39.62 90 top
C374  0.1uF  [C0402]  102.62 39.37 90 top
C375  1.5pF  [C0402]  169.93 40.64 90 top
C376  10uF  [C0603]  42.8 33.02 0 bottom
C377  47uF  [C0805]  110.62 37.21 90 top
C378  0.1uF  [C0402]  102.62 35.18 90 top
C379  0.1uF  [C0402]  102.62 33.78 90 top
C380  1000uF  [C_2P_244_295X177]  109.09 33.53 270 top
C381  22uF  [C1206-1]  137.16 33.15 90 top
C382  0.1uF  [C0402]  145.16 36.07 270 top
C383  0.1uF  [C0402]  136.09 36.22 180 top
C384  0.1uF  [C0402]  153.92 174.12 0 bottom
C385  10uF  [C0805]  132.84 171.58 0 bottom
C386  10uF  [C0805]  130.3 171.58 0 bottom
C387  NL/56pF  [C0603]  105.03 170.69 90 bottom
C388  0.1uF  [C0402]  155.96 169.93 0 bottom
C389  0.1uF  [C0402]  151.66 169.93 180 bottom
C390  100uF  [C1206-1]  114.94 169.93 90 bottom
C391  0.01uF  [C0402]  127.25 167 90 bottom
C392  0.1uF  [C0402]  105.79 166.37 180 bottom
C393  0.1uF  [C0402]  144.53 163.32 90 bottom
C394  0.1uF  [C0402]  146.69 162.18 180 bottom
C395  0.1uF  [C0402]  47.93 161.93 270 bottom
C396  0.1uF  [C0402]  47.93 160.55 270 bottom
C397  10uF  [C0603]  48.31 159 270 bottom
C398  0.1uF  [C0402]  146.69 159 0 bottom
C399  100uF  [C1206-1]  117.09 158.5 180 bottom
C400  100uF  [C1206-1]  128.14 156.34 0 bottom
C401  0.1uF  [C0402]  134.37 155.7 270 bottom
C402  0.1uF  [C0402]  146.69 155.57 180 bottom
C403  NL/10uF  [C1206-1]  117.09 155.57 180 bottom
C404  0.47uF  [C0402]  57.4 157.23 180 bottom
C405  0.47uF  [C0402]  56.01 157.23 0 bottom
C406  0.47uF  [C0402]  54.61 157.23 180 bottom
C407  0.47uF  [C0402]  53.21 157.23 0 bottom
C408  0.47uF  [C0402]  51.82 157.23 0 bottom
C409  4.7uF  [C0603]  70.87 157.1 90 bottom
C410  1uF  [C0603]  67.06 157.1 90 bottom
C411  1uF  [C0603]  63.63 157.1 90 bottom
C412  1uF  [C0603]  59.82 157.1 270 bottom
C413  10uF  [C1206-1]  128.14 153.42 0 bottom
C414  0.1uF  [C0402]  155.96 152.15 0 bottom
C415  2.2uF  [C0402]  148.34 151.26 180 bottom
C416  0.1uF  [C0402]  163.96 150.37 270 bottom
C417  0.1uF  [C0402]  158.5 149.73 180 bottom
C418  0.1uF  [C0402]  156.92 139.7 90 bottom
C419  47uF  [C0805]  135.38 147.83 90 bottom
C420  4.7uF  [C1206-1]  121.13 146.08 90 bottom
C421  0.1uF  [C0402]  148.46 149.35 270 bottom
C422  47uF  [C0805]  73.03 148.46 90 bottom
C423  1uF  [C0603]  86.49 147.32 270 bottom
C424  0.1uF  [C0402]  163.7 143.76 270 bottom
C425  22uF  [C1206-1]  82.17 146.94 90 bottom
C426  22uF  [C1206-1]  77.7 146.69 0 bottom
C427  0.1uF  [C0402]  145.47 142.62 270 top
C428  220uF  [C_2P_114_138X118]  72.77 145.54 0 bottom
C429  4.7uF  [C1206-1]  57.84 144.27 0 bottom
C430  0.1uF  [C0603]  119.48 140.87 270 bottom
C431  220uF  [C_2P_114_138X118]  72.77 142.11 0 bottom
C432  470uF  [C_2P_244_287X177_H110]  127 139.32 90 bottom
C433  100uF  [C1206-1]  64.9 141.73 180 bottom
C434  0.1uF  [C0402]  53.59 140.34 270 bottom
C435  470uF  [C_2P_244_287X177_H110]  86.92 137.92 0 bottom
C436  470uF  [C_2P_244_287X177_H110]  81.92 138.43 0 bottom
C437  1000uF  [C_2P_244_295X177]  64.36 137.97 90 bottom
C438  0.1uF  [C0402]  68.45 141.1 90 bottom
C439  0.1uF  [C0402]  128.65 128.91 90 bottom
C440  0.1uF  [C0402]  82.04 130.3 270 bottom
C441  4.7uF  [C0603]  126.49 128.52 180 bottom
C442  0.1uF  [C0402]  70.1 123.32 270 bottom
C443  0.1uF  [C0402]  70.1 124.71 270 bottom
C444  0.1uF  [C0402]  70.1 126.11 270 bottom
C445  0.1uF  [C0402]  70.1 127.51 270 bottom
C446  0.1uF  [C0402]  56.26 134.11 0 bottom
C447  0.1uF  [C0402]  54.86 134.11 0 bottom
C448  0.1uF  [C0402]  53.47 134.11 0 bottom
C449  0.1uF  [C0402]  50.67 134.11 0 bottom
C450  0.1uF  [C0402]  52.07 134.1 0 bottom
C451  47uF  [C0805]  89.79 131.19 90 bottom
C452  47uF  [C0805]  78.92 131.65 270 bottom
C453  1000pF  [C0402]  105.41 128.14 180 bottom
C454  0.1uF  [C0402]  116.08 127.38 90 bottom
C455  0.1uF  [C0402]  68.96 121.67 180 bottom
C456  0.1uF  [C0402]  77.34 129.67 180 bottom
C457  0.1uF  [C0402]  79.02 129.51 90 bottom
C458  1000pF  [C0402]  105.41 126.11 180 bottom
C459  0.1uF  [C0402]  56.26 131.83 270 bottom
C460  0.1uF  [C0402]  116.08 125.98 90 bottom
C461  560pF  [C0402]  90.04 129.29 270 bottom
C462  0.1uF  [C0402]  67.56 121.67 180 bottom
C463  0.1uF  [C0402]  56.26 130.42 270 bottom
C464  0.1uF  [C0402]  66.17 121.67 180 bottom
C465  0.1uF  [C0402]  107.7 124.33 270 bottom
C466  0.1uF  [C0402]  64.39 121.67 180 bottom
C467  0.1uF  [C0402]  64.26 128.02 0 bottom
C468  0.1uF  [C0402]  56.26 128.14 270 bottom
C469  0.1uF  [C0402]  49.78 128.02 90 bottom
C470  0.1uF  [C0402]  63.63 123.32 90 bottom
C471  0.1uF  [C0402]  63.63 124.97 90 bottom
C472  0.1uF  [C0402]  54.1 127.5 180 bottom
C473  0.1uF  [C0402]  52.58 127.5 180 bottom
C474  0.1uF  [C0402]  65.66 128.02 0 bottom
C475  0.1uF  [C0402]  156.84 119.89 180 bottom
C476  1uF  [C0402]  155.45 119.89 0 bottom
C477  0.1uF  [C0402]  93.09 122.56 0 bottom
C478  0.1uF  [C0402]  91.69 122.56 0 bottom
C479  0.1uF  [C0402]  90.3 122.56 0 bottom
C480  0.1uF  [C0402]  88.52 122.56 0 bottom
C481  0.1uF  [C0402]  86.59 122.91 0 bottom
C482  0.1uF  [C0402]  85.24 122.91 0 bottom
C483  0.1uF  [C0402]  92.71 120.4 270 bottom
C484  1uF  [C0402]  85.27 121.39 270 bottom
C485  0.1uF  [C0402]  92.71 118.87 270 bottom
C486  0.1uF  [C0402]  85.27 119.99 90 bottom
C487  0.1uF  [C0402]  80.11 118.34 90 bottom
C488  0.1uF  [C0402]  85.24 118.59 90 bottom
C489  0.1uF  [C0402]  85.24 117.2 90 bottom
C490  0.1uF  [C0402]  158.37 109.73 0 bottom
C491  0.1uF  [C0402]  156.97 109.73 180 bottom
C492  0.1uF  [C0402]  155.57 109.73 180 bottom
C493  0.1uF  [C0402]  154.18 109.73 0 bottom
C494  0.1uF  [C0402]  79.25 108.71 0 bottom
C495  0.1uF  [C0402]  124.46 107.82 270 bottom
C496  0.1uF  [C0402]  93.6 112.52 0 bottom
C497  100pF  [C0402]  87.5 110.57 0 top
C498  100uF  [C1206-1]  82.35 111.84 270 top
C499  0.1uF  [C0402]  55.75 109.47 180 bottom
C500  0.1uF  [C0402]  54.36 109.47 180 bottom
C501  0.1uF  [C0402]  32.64 103.76 0 bottom
C502  0.1uF  [C0402]  40.01 112.57 180 bottom
C503  470uF  [C_2P_244_287X177_H110]  26.29 102.11 90 bottom
C504  22uF  [C1206-1]  15.24 101.98 180 bottom
C505  0.1uF  [C0402]  44.7 101.73 270 bottom
C506  0.1uF  [C0402]  38.73 112.57 180 bottom
C507  0.1uF  [C0402]  134.37 100.84 90 bottom
C508  4.7uF  [C0603]  26.92 107.82 90 bottom
C509  47uF  [C0805]  26.8 105.79 270 bottom
C510  0.1uF  [C0402]  44.7 100.33 270 bottom
C511  0.1uF  [C0402]  46.86 99.69 270 bottom
C512  0.1uF  [C0402]  134.37 99.38 90 bottom
C513  0.1uF  [C0402]  46.86 98.3 270 bottom
C514  0.01uF  [C0402]  75.56 97.92 0 bottom
C515  560pF  [C0402]  73.53 97.92 0 bottom
C516  560pF  [C0402]  71.5 97.92 0 bottom
C517  0.1uF  [C0402]  44.7 97.16 270 bottom
C518  560pF  [C0402]  69.47 96.9 0 bottom
C519  560pF  [C0402]  67.92 96.52 90 bottom
C520  0.01uF  [C0402]  71.42 85.88 0 bottom
C521  0.1uF  [C0402]  88.99 95.4 270 bottom
C522  0.01uF  [C0402]  34.54 99.44 0 bottom
C523  0.1uF  [C0402]  44.7 95.76 270 bottom
C524  0.1uF  [C0402]  47.24 93.85 270 bottom
C525  0.1uF  [C0402]  86.49 82.93 0 bottom
C526  0.01uF  [C0402]  63.12 96.27 270 bottom
C527  0.01uF  [C0402]  61.52 96.9 0 bottom
C528  1000pF  [C0402]  74.93 95.88 180 bottom
C529  0.01uF  [C0402]  73.53 95.88 180 bottom
C530  560pF  [C0402]  71.5 95.88 180 bottom
C531  0.1uF  [C0402]  88.98 93.47 270 bottom
C532  100uF  [C1206-1]  85.85 107.95 0 bottom
C533  560pF  [C0402]  67.06 95.38 90 bottom
C534  0.1uF  [C0402]  47.24 95.25 270 bottom
C535  560pF  [C0402]  69.98 95.25 270 bottom
C536  1000pF  [C0402]  65.15 95.12 90 bottom
C537  22uF  [C1206-1]  15.24 94.87 0 bottom
C538  0.1uF  [C0402]  88.57 83.92 0 bottom
C539  560pF  [C0402]  63.12 95.12 270 bottom
C540  560pF  [C0402]  77.85 95.25 0 bottom
C541  560pF  [C0402]  79.12 95.25 0 bottom
C542  0.01uF  [C0402]  83.06 96.27 270 bottom
C543  0.1uF  [C0402]  89.03 90.47 270 bottom
C544  470uF  [C_2P_244_287X177_H110]  26.42 93.6 90 bottom
C545  0.01uF  [C0402]  78.03 97.4 90 bottom
C546  0.01uF  [C0402]  77.47 98.91 0 bottom
C547  0.01uF  [C0402]  79.5 98.93 0 bottom
C548  560pF  [C0402]  81.15 95 270 bottom
C549  0.01uF  [C0402]  81.15 96.27 270 bottom
C550  0.01uF  [C0402]  83.06 97.41 270 bottom
C551  100uF  [C1206-1]  85.85 110.74 0 bottom
C552  560pF  [C0402]  83.03 98.81 270 bottom
C553  560pF  [C0402]  59.74 90.75 180 bottom
C554  560pF  [C0402]  86.55 89.9 0 bottom
C555  0.1uF  [C0402]  79.45 96.95 0 bottom
C556  560pF  [C0402]  76.45 95.91 0 bottom
C557  4.7uF  [C0603]  32.77 91.82 180 bottom
C558  0.01uF  [C0402]  37.97 91.82 0 bottom
C559  0.01uF  [C0402]  74.04 90.42 90 bottom
C560  0.1uF  [C0402]  71.88 90.93 270 bottom
C561  0.1uF  [C0402]  69.95 87.88 180 bottom
C562  560pF  [C0402]  85.01 98.93 90 bottom
C563  560pF  [C0402]  66.93 89.38 90 bottom
C564  0.1uF  [C0402]  65.02 90.55 90 bottom
C565  0.01uF  [C0402]  85.09 90.55 0 bottom
C566  0.1uF  [C0402]  59.99 87.88 180 bottom
C567  0.1uF  [C0402]  87.05 92.58 270 bottom
C568  0.1uF  [C0402]  47.24 89.59 90 bottom
C569  27pF  [C0402]  149.48 90.3 270 bottom
C570  27pF  [C0402]  145.41 90.3 90 bottom
C571  0.1uF  [C0402]  75.56 89.92 0 bottom
C572  0.01uF  [C0402]  153.8 89.66 270 bottom
C573  560pF  [C0402]  64.97 89.36 90 bottom
C574  0.1uF  [C0402]  66.93 90.55 270 bottom
C575  47nF  [C0402]  68.99 89.41 270 bottom
C576  47uF  [C0805]  90.55 114.05 180 bottom
C577  0.1uF  [C0402]  47.24 85.98 90 bottom
C578  10uF  [C0603]  92.58 115.06 0 bottom
C579  0.1uF  [C0402]  47.24 88.19 90 bottom
C580  0.1uF  [C0402]  58.67 87.07 0 bottom
C581  0.01uF  [C0402]  85.09 88.77 180 bottom
C582  0.1uF  [C0402]  26.16 88.01 180 bottom
C583  560pF  [C0402]  75.95 87.88 180 bottom
C584  0.01uF  [C0402]  74.52 87.88 180 bottom
C585  0.01uF  [C0402]  69.98 90.93 270 bottom
C586  560pF  [C0402]  68.58 87.88 180 bottom
C587  560pF  [C0402]  66.93 87.88 0 bottom
C588  0.1uF  [C0402]  65.02 87.88 90 bottom
C589  0.1uF  [C0402]  47.24 84.58 90 bottom
C590  0.1uF  [C0402]  44.83 84.33 90 bottom
C591  10uF  [C0603]  94.23 115.06 0 bottom
C592  0.1uF  [C0402]  87.5 86.89 0 bottom
C593  4.7uF  [C0603]  109.6 82.8 90 bottom
C594  0.1uF  [C0402]  65.02 86.49 90 bottom
C595  47uF  [C0805]  85.72 114.05 180 bottom
C596  0.1uF  [C0402]  44.83 82.93 90 bottom
C597  560pF  [C0402]  68.28 86.06 180 bottom
C598  560pF  [C0402]  66.9 86.03 180 bottom
C599  0.1uF  [C0402]  59.44 84.84 180 bottom
C600  1uF  [C0402]  70 85.45 90 bottom
C601  0.1uF  [C0402]  65.02 85.34 90 bottom
C602  0.01uF  [C0402]  85.09 84.96 0 bottom
C603  0.01uF  [C0402]  76.58 84.94 180 bottom
C604  560pF  [C0402]  75.31 84.94 180 bottom
C605  560pF  [C0402]  74.04 84.94 180 bottom
C606  0.01uF  [C0402]  72.77 84.94 180 bottom
C607  0.01uF  [C0402]  79.53 80.95 180 bottom
C608  0.01uF  [C0402]  67.11 84.45 90 bottom
C609  0.1uF  [C0402]  71.5 83.95 180 bottom
C610  0.01uF  [C0402]  69.85 83.95 180 bottom
C611  0.01uF  [C0402]  68.58 83.95 180 bottom
C612  0.01uF  [C0402]  87 84.34 270 bottom
C613  0.1uF  [C0402]  65.02 81.91 90 bottom
C614  47uF  [C0805]  88.14 114.05 180 bottom
C615  0.01uF  [C0402]  76.58 82.93 180 bottom
C616  0.1uF  [C0402]  59.82 82.93 180 bottom
C617  1uF  [C0402]  67.01 82.55 90 bottom
C618  4.7uF  [C0603]  85.17 82.45 0 bottom
C619  0.1uF  [C0402]  71.55 81.97 180 bottom
C620  0.01uF  [C0402]  85.22 76.96 0 bottom
C621  560pF  [C0402]  74.57 81.91 180 bottom
C622  0.01uF  [C0402]  73.36 81.91 180 bottom
C623  0.1uF  [C0402]  69.98 81.91 90 bottom
C624  560pF  [C0402]  65.02 83.44 90 bottom
C625  2.2uF  [C0402]  125.73 81.66 0 bottom
C626  0.1uF  [C0402]  58.93 81.48 90 bottom
C627  0.1uF  [C0402]  36.58 85.85 0 bottom
C628  0.01uF  [C0402]  35.18 85.85 0 bottom
C629  560pF  [C0402]  33.78 85.85 0 bottom
C630  0.1uF  [C0402]  76.53 80.95 0 bottom
C631  0.01uF  [C0402]  85.09 87 0 bottom
C632  0.1uF  [C0402]  80.98 80.92 0 bottom
C633  560pF  [C0402]  69.98 80.65 90 bottom
C634  560pF  [C0402]  67.06 80.65 90 bottom
C635  0.01uF  [C0402]  72.03 80.39 270 bottom
C636  0.1uF  [C0402]  65.02 80.39 90 bottom
C637  0.1uF  [C0402]  59.18 79.38 90 bottom
C638  560pF  [C0402]  88.98 82.42 270 bottom
C639  1uF  [C0402]  77.9 79.93 0 bottom
C640  0.01uF  [C0402]  73.66 79.88 180 bottom
C641  0.1uF  [C0402]  69.98 79.38 90 bottom
C642  100uF  [C1206-1]  45.97 75.69 180 bottom
C643  0.1uF  [C0402]  65.02 78.61 90 bottom
C644  0.01uF  [C0402]  153.8 78.99 270 bottom
C645  47nF  [C0402]  80.52 78.94 0 bottom
C646  0.1uF  [C0402]  76.56 78.92 0 bottom
C647  0.1uF  [C0402]  68.45 78.87 180 bottom
C648  0.1uF  [C0402]  72.03 79.07 270 bottom
C649  47nF  [C0402]  66.93 78.59 90 bottom
C650  0.01uF  [C0402]  88.98 92.33 270 bottom
C651  47nF  [C0402]  73.56 77.93 0 bottom
C652  0.01uF  [C0402]  24.26 77.72 270 bottom
C653  0.01uF  [C0402]  22.23 77.72 90 bottom
C654  10uF  [C0603]  110.36 57.4 270 bottom
C655  560pF  [C0402]  59.69 76.84 90 bottom
C656  47uF  [C0805]  113.92 43.81 270 bottom
C657  1uF  [C0402]  71.5 76.96 180 bottom
C658  0.1uF  [C0402]  70.23 77.85 180 bottom
C659  0.1uF  [C0402]  68.96 76.96 180 bottom
C660  47nF  [C0402]  67.69 76.96 180 bottom
C661  0.1uF  [C0402]  66.42 76.96 180 bottom
C662  0.01uF  [C0402]  65.23 76.96 180 bottom
C663  0.01uF  [C0402]  26.16 76.96 0 bottom
C664  560pF  [C0402]  64.03 76.94 0 bottom
C665  560pF  [C0402]  58.42 73.91 90 bottom
C666  0.1uF  [C0402]  134.11 76.77 90 bottom
C667  47nF  [C0402]  73.03 76.4 90 bottom
C668  0.1uF  [C0402]  47.24 72.77 270 bottom
C669  10uF  [C0603]  75.06 75.97 180 bottom
C670  0.1uF  [C0402]  99.8 79.48 0 bottom
C671  0.1uF  [C0402]  98.4 79.48 0 bottom
C672  0.1uF  [C0402]  110.49 58.8 270 bottom
C673  0.01uF  [C0402]  80.52 76.96 0 bottom
C674  0.1uF  [C0402]  76.53 75.9 180 bottom
C675  0.1uF  [C0402]  134.11 75.31 90 bottom
C676  0.01uF  [C0402]  73.61 74.93 0 bottom
C677  0.1uF  [C0402]  72.34 74.93 180 bottom
C678  0.01uF  [C0402]  67.06 69.47 270 bottom
C679  0.1uF  [C0402]  75.03 86.46 270 bottom
C680  560pF  [C0402]  72.87 86.74 270 bottom
C681  0.1uF  [C0402]  71.37 87.81 180 bottom
C682  0.1uF  [C0402]  72.92 89.33 90 bottom
C683  560pF  [C0402]  72.92 88.09 90 bottom
C684  0.1uF  [C0402]  75.06 83.39 90 bottom
C685  0.01uF  [C0402]  60.02 73.84 180 bottom
C686  0.1uF  [C0402]  47.24 71.37 270 bottom
C687  0.1uF  [C0402]  110.49 64.77 270 bottom
C688  0.1uF  [C0402]  21.08 73.91 180 bottom
C689  0.1uF  [C0402]  80.52 74.93 0 bottom
C690  560pF  [C0402]  77.09 74.42 90 bottom
C691  560pF  [C0402]  79.51 66.96 180 bottom
C692  560pF  [C0402]  73.03 67.18 270 bottom
C693  560pF  [C0402]  79.02 68.41 90 bottom
C694  560pF  [C0402]  77.03 67.43 90 bottom
C695  0.1uF  [C0402]  73.66 68.96 180 bottom
C696  560pF  [C0402]  68.48 68.96 180 bottom
C697  1uF  [C0402]  68.45 82.04 180 bottom
C698  0.01uF  [C0402]  84.48 97.28 180 bottom
C699  560pF  [C0402]  59.05 75.69 90 bottom
C700  0.1uF  [C0402]  85.52 73.86 0 bottom
C701  0.01uF  [C0402]  86.49 71.91 180 bottom
C702  0.1uF  [C0402]  110.49 63.37 270 bottom
C703  0.1uF  [C0402]  75.06 67.44 270 bottom
C704  560pF  [C0402]  76.96 69.47 270 bottom
C705  0.01uF  [C0402]  64.52 68.96 180 bottom
C706  560pF  [C0402]  72.52 68.96 180 bottom
C707  0.01uF  [C0402]  64.51 66.89 0 bottom
C708  1000pF  [C0402]  110.49 61.59 270 bottom
C709  0.01uF  [C0402]  75.08 69.47 270 bottom
C710  0.1uF  [C0402]  70.99 67.44 90 bottom
C711  560pF  [C0402]  110.49 60.2 270 bottom
C712  0.1uF  [C0402]  66.55 67.94 180 bottom
C713  0.01uF  [C0402]  61.47 67.94 180 bottom
C714  0.01uF  [C0402]  154.94 68.58 0 bottom
